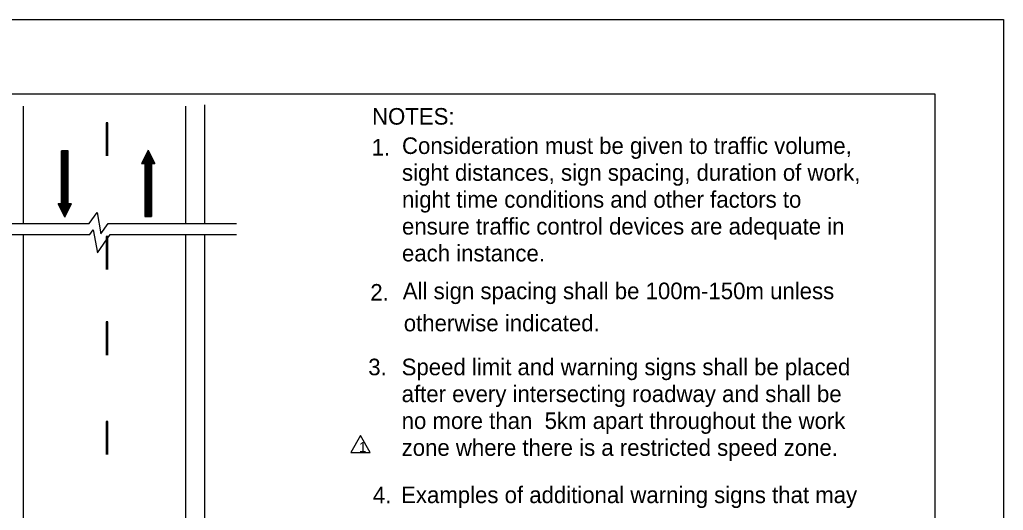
# Model space of a CAD drawing. Extents: x 1372 to 1588, y 125 to 404.
# Drawn here: x 1444.6 to 1588.1, y 332.4 to 404 of the extents above; entities that cross this region are included whole.
import ezdxf

# ---------------------------------------------------------------- set-up
doc = ezdxf.new("R2010")
doc.units = 0
for name, color, linetype in [('Level 1', 7, 'Continuous'), ('Level 10', 7, 'Continuous'), ('Level 2', 7, 'Continuous'), ('Level 44', 7, 'Continuous'), ('Level 60', 7, 'Continuous')]:
    doc.layers.add(name, color=color, linetype=linetype)

msp = doc.modelspace()

# ---------------------------------------------------------------- linework, layer by layer
at = {"layer": 'Level 1'}
msp.add_lwpolyline([(1494.29, 343.3), (1492.87, 340.83), (1495.71, 340.83)], close=True, dxfattribs=at)
at = {"layer": 'Level 10'}
for p, q in [((1445.05, 391.35), (1445.05, 374.24)), ((1468.76, 391.35), (1468.76, 374.24)), ((1471.51, 391.56), (1471.51, 374.24)), ((1450.68, 377.12), (1450.68, 384.86)), ((1451.65, 384.86), (1450.68, 384.86)), ((1450.68, 376.15), (1450.68, 384.86)), ((1450.8, 375.91), (1450.8, 384.86)), ((1450.92, 375.67), (1450.92, 384.86)), ((1451.04, 375.42), (1451.04, 384.86)), ((1451.16, 375.18), (1451.16, 384.86)), ((1451.28, 375.42), (1451.28, 384.86)), ((1451.4, 375.67), (1451.4, 384.86)), ((1451.52, 375.91), (1451.52, 384.86)), ((1451.65, 377.12), (1451.65, 384.86)), ((1451.65, 376.15), (1451.65, 384.86)), ((1463.3, 384.94), (1462.33, 383)), ((1463.18, 384.69), (1463.18, 375.26)), ((1463.3, 384.94), (1463.3, 375.26)), ((1463.3, 384.94), (1464.27, 383)), ((1463.42, 384.69), (1463.42, 375.26)), ((1462.45, 383.24), (1462.45, 383)), ((1462.57, 383.49), (1462.57, 383)), ((1462.69, 383.73), (1462.69, 383)), ((1462.82, 383.97), (1462.82, 375.26)), ((1462.94, 384.21), (1462.94, 375.26)), ((1463.06, 384.45), (1463.06, 375.26)), ((1463.54, 384.45), (1463.54, 375.26)), ((1463.66, 384.21), (1463.66, 375.26)), ((1463.78, 383.97), (1463.78, 375.26)), ((1463.9, 383.73), (1463.9, 383)), ((1464.03, 383.49), (1464.03, 383)), ((1464.15, 383.24), (1464.15, 383)), ((1462.33, 383), (1462.82, 383)), ((1462.82, 383), (1462.82, 375.26)), ((1463.78, 383), (1463.78, 375.26)), ((1463.78, 383), (1464.27, 383)), ((1451.16, 375.18), (1450.19, 377.12)), ((1450.68, 377.12), (1450.19, 377.12)), ((1450.32, 376.87), (1450.32, 377.12)), ((1450.44, 376.63), (1450.44, 377.12)), ((1450.56, 376.39), (1450.56, 377.12)), ((1451.16, 375.18), (1452.13, 377.12)), ((1452.13, 377.12), (1451.65, 377.12)), ((1451.77, 376.39), (1451.77, 377.12)), ((1451.89, 376.63), (1451.89, 377.12)), ((1452.01, 376.87), (1452.01, 377.12)), ((1462.82, 375.26), (1463.78, 375.26)), ((1445.05, 372.63), (1445.05, 157.87)), ((1468.76, 372.63), (1468.76, 157.87)), ((1471.51, 372.63), (1471.51, 202.79))]:
    msp.add_line(p, q, dxfattribs=at)
at = {"layer": 'Level 2'}
for p, q in [((1457.15, 388.93), (1457.15, 384.09)), ((1457.44, 388.93), (1457.15, 388.93)), ((1457.44, 384.09), (1457.44, 388.93)), ((1457.15, 372.34), (1457.15, 367.5)), ((1457.44, 372.34), (1457.15, 372.34)), ((1457.44, 367.5), (1457.44, 372.34)), ((1457.15, 359.87), (1457.15, 355.04)), ((1457.44, 359.87), (1457.15, 359.87)), ((1457.44, 355.04), (1457.44, 359.87)), ((1457.15, 345.36), (1457.15, 340.52)), ((1457.44, 345.36), (1457.15, 345.36)), ((1457.44, 340.52), (1457.44, 345.36))]:
    msp.add_line(p, q, dxfattribs=at)
at = {"layer": 'Level 44'}
for p, q in [((1454.71, 374.24), (1455.85, 375.86)), ((1455.85, 375.86), (1456.41, 372.74)), ((1437.62, 374.24), (1454.71, 374.24)), ((1454.8, 372.63), (1455.3, 373.32)), ((1455.3, 373.32), (1455.89, 369.97)), ((1456.41, 372.74), (1457.47, 374.24)), ((1457.47, 374.24), (1476.18, 374.24)), ((1437.62, 372.63), (1454.8, 372.63)), ((1455.89, 369.97), (1457.77, 372.63)), ((1457.77, 372.63), (1476.18, 372.63))]:
    msp.add_line(p, q, dxfattribs=at)
at = {"layer": 'Level 60'}
for points in [[(1372.06, 403.98), (1588.06, 403.98), (1588.06, 124.98), (1372.06, 124.98)], [(1391.18, 393.17), (1578.06, 393.17), (1578.06, 135.79), (1391.18, 135.79)]]:
    msp.add_lwpolyline(points, close=True, dxfattribs=at)

# ---------------------------------------------------------------- texts
at = {"layer": 'Level 1'}
msp.add_text('1', height=1.45, rotation=360, dxfattribs=at).set_placement((1494.07, 340.89))
at = {"layer": 'Level 10'}
for s, p in [('NOTES:', (1495.96, 388.66)), ('1.', (1495.91, 384.14)), ('Consideration must be given to traffic volume,', (1500.33, 384.38)), ('sight distances, sign spacing, duration of work,', (1500.33, 380.46)), ('night time conditions and other factors to', (1500.33, 376.54)), ('ensure traffic control devices are adequate in', (1500.33, 372.62)), ('each instance.', (1500.33, 368.7)), ('2.', (1495.71, 362.98)), ('All sign spacing shall be 100m-150m unless', (1500.45, 363.19)), ('otherwise indicated.', (1500.59, 358.5)), ('3.', (1495.41, 352.09)), ('Speed limit and warning signs shall be placed ', (1500.28, 352.09)), ('after every intersecting roadway and shall be ', (1500.28, 348.17)), ('no more than  5km apart throughout the work ', (1500.28, 344.25)), ('zone where there is a restricted speed zone.', (1500.28, 340.33)), ('4.', (1496.08, 333.4)), ('Examples of additional warning signs that may', (1500.2, 333.43))]:
    msp.add_text(s, height=2.419, dxfattribs=at).set_placement(p)

doc.saveas('drawing.dxf')
